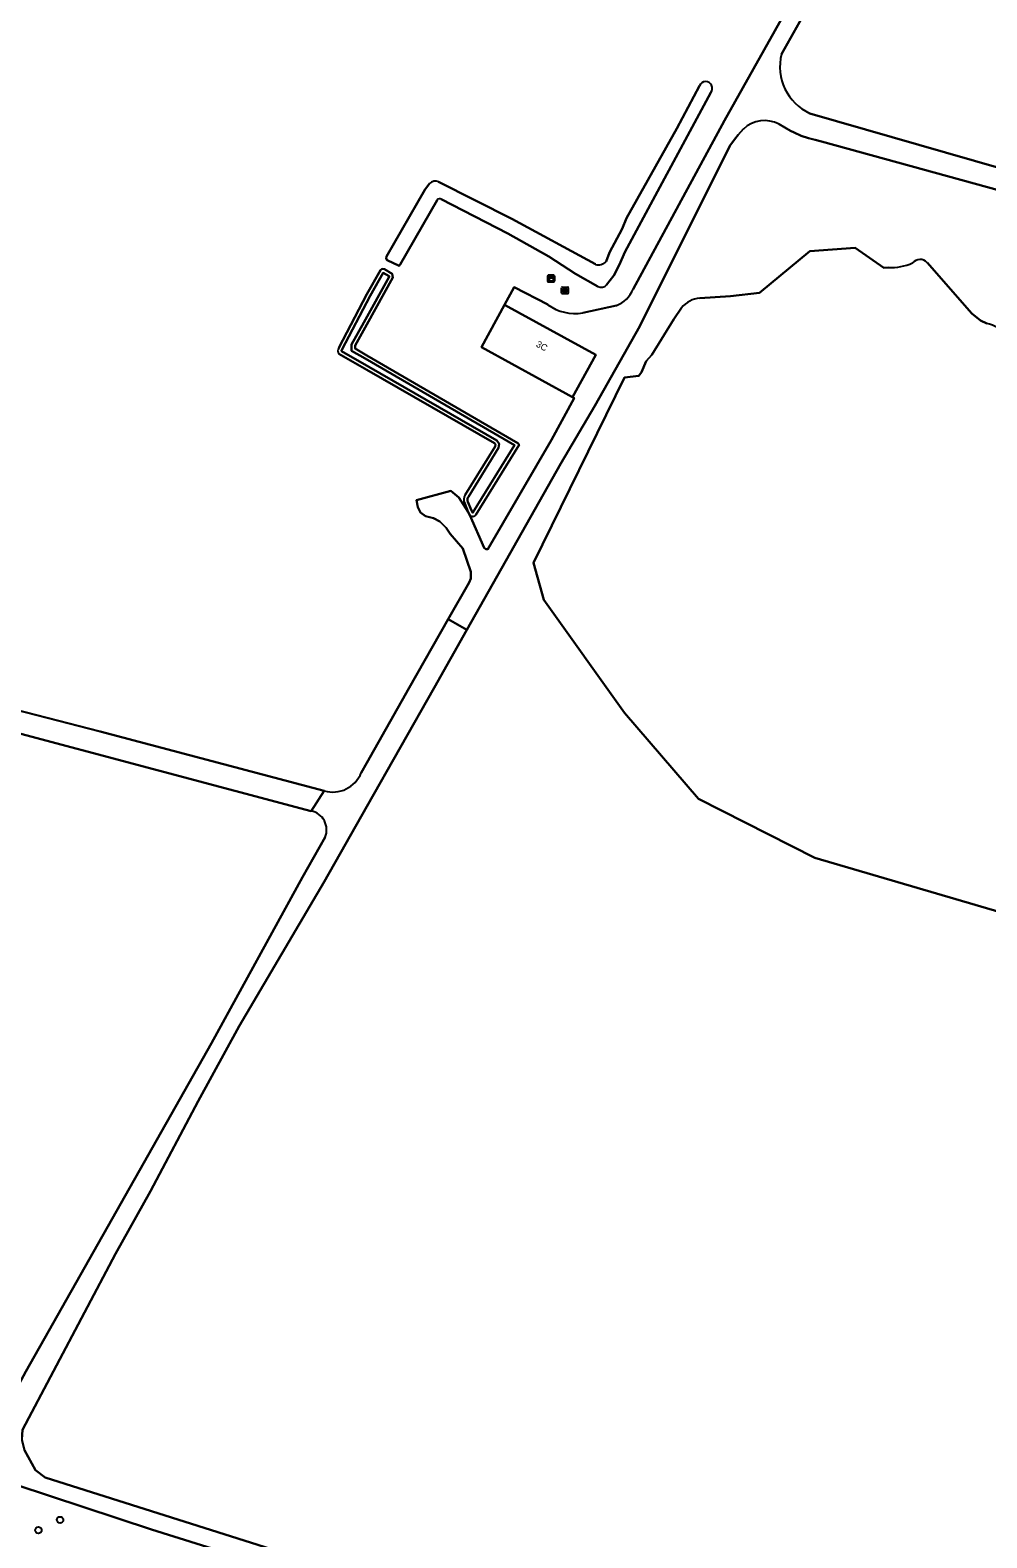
# Model space of a CAD drawing. Extents: x 156502 to 159075, y 384229 to 386100.
# Drawn here: x 157448.6 to 157594.6, y 384870.4 to 385100.3 of the extents above; entities that cross this region are included whole.
import ezdxf

# ---------------------------------------------------------------- set-up
doc = ezdxf.new("R2010")
doc.units = 0
for name, color, linetype in [('IMGEO_Boom', 7, 'Continuous'), ('IMGEO_Gemengd_bos', 7, 'Continuous'), ('IMGEO_Greppel_droge_sloot', 7, 'Continuous'), ('IMGEO_Kast', 7, 'Continuous'), ('IMGEO_Loofbos', 7, 'Continuous'), ('IMGEO_Meer_plas_ven_vijver', 7, 'Continuous'), ('IMGEO_Oever', 7, 'Continuous'), ('IMGEO_Pand', 7, 'Continuous'), ('IMGEO_Pand_nummerreeks', 7, 'Continuous'), ('IMGEO_Rijbaan_lokaal_gesloten', 7, 'Continuous'), ('IMGEO_Rijbaan_lokaal_onverhard', 7, 'Continuous'), ('IMGEO_Rioolput', 7, 'Continuous'), ('IMGEO_Voetpad_onverhard', 7, 'Continuous')]:
    doc.layers.add(name, color=color, linetype=linetype)

msp = doc.modelspace()

# ---------------------------------------------------------------- linework, layer by layer
at = {"layer": 'IMGEO_Boom'}
for centre in [(157453.19, 384873.13), (157449.89, 384871.57)]:
    msp.add_circle(centre, 0.489, dxfattribs=at)
at = {"layer": 'IMGEO_Gemengd_bos'}
for points in [[(157619.03, 385198.31), (157603.77, 385169.97), (157595.58, 385155.12), (157590.55, 385145.45), (157589.49, 385143.45), (157567.34, 385103.96), (157563.24, 385096.66)], [(157554.56, 385086.54), (157565.02, 385105.23), (157569.42, 385113.09), (157500, 385132.38), (157470.27, 385140.64), (157454.36, 385144.87), (157448.51, 385145.98)], [(157536.51, 385065.03), (157537.01, 385066.38), (157538.91, 385069.99), (157539.6, 385071.63), (157547.26, 385085.3), (157550.73, 385091.84)], [(157552.46, 385090.81), (157539.32, 385066.46), (157538.54, 385064.55), (157537.65, 385062.89), (157536.56, 385061.49)], [(157540.59, 385060.8), (157554.56, 385086.54)], [(157567.57, 385087.61), (157596.76, 385079.21), (157621.45, 385071.9), (157659.74, 385061.09), (157700.37, 385049.93), (157754.96, 385035.18)], [(157557.42, 385085.24), (157556.63, 385084.36), (157556.08, 385083.63), (157555.36, 385082.68), (157541.62, 385055.15), (157534.74, 385043), (157529.56, 385034.25), (157515.26, 385008.86), (157510.25, 385000), (157500, 384981.92), (157493.48, 384970.42), (157480.53, 384948.41), (157474.26, 384937.01), (157466.98, 384923.25), (157461.66, 384913.7), (157447.44, 384886.89), (157447.37, 384885.41), (157447.76, 384883.78), (157449.47, 384880.72), (157450.91, 384879.62), (157588.71, 384836)], [(157761.76, 385030.22), (157747.64, 385033.88), (157701.75, 385046.75), (157698.89, 385047.59), (157679.73, 385052.63), (157623.49, 385068.42), (157569.36, 385083.33), (157568.38, 385083.57), (157567.38, 385083.83), (157566.24, 385084.2), (157565.17, 385084.7), (157564.62, 385084.98), (157563.75, 385085.49), (157562.86, 385085.96)], [(157510.71, 385074.39), (157505.07, 385064.55), (157504.9, 385064.37), (157503.11, 385065.26), (157502.95, 385065.5), (157503.01, 385065.78), (157508.81, 385075.97), (157509.56, 385076.91)], [(157510.93, 385077.18), (157522.12, 385071.55), (157534.85, 385064.6)], [(157535.23, 385061.24), (157531.83, 385063.14), (157527.77, 385065.77), (157521.5, 385069.31), (157511.34, 385074.52)], [(157550.8, 385059.42), (157555.48, 385059.74), (157559.89, 385060.27), (157567.56, 385066.62), (157574.5, 385067.13), (157578.83, 385064.05), (157579.55, 385064.1)], [(157495.71, 385051.85), (157500, 385060.07), (157502.06, 385063.71), (157502.33, 385063.89), (157502.66, 385063.85), (157503.86, 385063.13), (157503.97, 385062.59), (157500, 385055.45), (157498.21, 385052.24), (157498.21, 385051.74), (157500, 385050.7), (157523.04, 385037.34), (157523.2, 385037.07), (157516.63, 385026.42)], [(157585.44, 385064.86), (157592.25, 385057.12), (157593.58, 385056.04), (157594.56, 385055.57)], [(157515.72, 385026.34), (157517.86, 385021.39), (157518.12, 385021.15), (157518.42, 385021.19), (157528.15, 385037.83), (157531.62, 385044.19), (157531.37, 385044.36), (157517.47, 385051.98), (157521.01, 385058.43), (157522.48, 385061.11), (157527.58, 385058.45)], [(157604.79, 384970.83), (157604.56, 384970.51), (157602.5, 384964.09), (157568.33, 384974.11), (157550.6, 384983.1), (157539.29, 384996.21), (157526.96, 385013.43), (157525.42, 385019.08), (157539.29, 385047.34), (157541.49, 385047.59), (157541.86, 385048.15), (157542.61, 385049.83), (157543.45, 385050.79), (157546.8, 385056.26), (157547.98, 385057.95)], [(157532.92, 385057.18), (157538.06, 385058.32)], [(157515.01, 385029.45), (157519.56, 385036.83), (157519.6, 385037.11), (157519.44, 385037.35), (157500, 385048.52), (157495.74, 385050.96)], [(157499.14, 384987.07), (157500, 384988.58), (157506.45, 385000), (157512.38, 385010.47), (157515.58, 385016.07), (157515.85, 385016.71), (157515.85, 385017.73), (157514.62, 385021.26), (157512.72, 385023.49), (157512.1, 385024.43), (157511.14, 385025.37), (157510.15, 385025.89), (157508.93, 385026.22), (157508.18, 385026.78), (157507.79, 385027.58), (157507.58, 385028.62), (157512.78, 385030.05), (157514.01, 385029.03), (157515.45, 385026.82), (157514.91, 385028.14)], [(157433.42, 385000), (157459.32, 384993.37), (157493.49, 384984.32)]]:
    msp.add_lwpolyline(points, dxfattribs=at)
for centre, radius, start, end in [((157570.83, 385094.73), 7.83, 165.6966, 245.3534), ((157551.67, 385091.45), 1.02, 320.75, 157.7513), ((157560.63, 385081.87), 4.65, 61.3849, 133.6498), ((157510.43, 385076.1), 1.19, 64.7657, 137.0208), ((157511.09, 385074.15), 0.449, 55.8892, 148.6329), ((157535.32, 385066.21), 1.68, 253.8994, 315.2296), ((157579.8, 385072.58), 8.49, 268.2806, 293.8488), ((157584.35, 385063.89), 1.45, 41.8437, 140.3958), ((157535.75, 385062.14), 1.04, 239.4436, 321.2719), ((157536.29, 385062.65), 4.69, 292.2098, 336.6936), ((157551, 385055.59), 3.84, 92.8928, 141.9271), ((157531.79, 385064.29), 7.2, 234.2693, 279.0667), ((157592.67, 385048.11), 7.7, 49.5127, 75.8056), ((157496.32, 385051.43), 0.741, 145.3523, 218.5394), ((157516.02, 385028.72), 1.25, 144.2193, 207.5408), ((157516.14, 385026.77), 0.602, 225.6527, 325.0861), ((157494.79, 384988.82), 4.69, 253.7973, 338.0784)]:
    msp.add_arc(centre, radius, start, end, dxfattribs=at)
at = {"layer": 'IMGEO_Greppel_droge_sloot'}
for points in [[(157550.73, 385091.84), (157547.26, 385085.3), (157539.6, 385071.63), (157538.91, 385069.99), (157537.01, 385066.38), (157536.51, 385065.03)], [(157536.56, 385061.49), (157537.65, 385062.89), (157538.54, 385064.55), (157539.32, 385066.46), (157552.46, 385090.81)], [(157509.56, 385076.91), (157508.81, 385075.97), (157503.01, 385065.78), (157502.95, 385065.5), (157503.11, 385065.26), (157504.9, 385064.37), (157505.07, 385064.55), (157510.71, 385074.39)], [(157534.85, 385064.6), (157522.12, 385071.55), (157510.93, 385077.18)], [(157511.34, 385074.52), (157521.5, 385069.31), (157527.77, 385065.77), (157531.83, 385063.14), (157535.23, 385061.24)]]:
    msp.add_lwpolyline(points, dxfattribs=at)
msp.add_lwpolyline([(157496.14, 385051.37), (157500.28, 385048.99), (157519.83, 385037.76), (157520.18, 385037.24), (157520.09, 385036.64), (157515.47, 385029.14), (157515.43, 385029.08), (157515.4, 385029.03), (157515.37, 385028.97), (157515.35, 385028.91), (157515.34, 385028.85), (157515.33, 385028.79), (157515.33, 385028.73), (157515.33, 385028.67), (157515.33, 385028.61), (157515.35, 385028.55), (157515.36, 385028.49), (157515.39, 385028.43), (157515.41, 385028.38), (157515.95, 385027.06), (157516.14, 385026.72), (157516.14, 385026.72), (157516.15, 385026.72), (157516.15, 385026.72), (157516.15, 385026.72), (157516.16, 385026.73), (157516.16, 385026.73), (157516.17, 385026.73), (157516.17, 385026.73), (157516.17, 385026.73), (157516.18, 385026.74), (157522.51, 385037.01), (157499.72, 385050.22), (157497.66, 385051.42), (157497.66, 385052.38), (157499.52, 385055.72), (157503.39, 385062.68), (157503.37, 385062.78), (157502.47, 385063.31), (157500.49, 385059.8), (157496.18, 385051.55), (157496.17, 385051.54), (157496.16, 385051.53), (157496.15, 385051.51), (157496.14, 385051.5), (157496.14, 385051.48), (157496.13, 385051.47), (157496.13, 385051.45), (157496.13, 385051.43), (157496.13, 385051.42), (157496.13, 385051.4), (157496.13, 385051.39)], close=True, dxfattribs=at)
for centre, radius, start, end in [((157551.67, 385091.45), 1.02, 320.75, 157.7513), ((157510.43, 385076.1), 1.19, 64.7657, 137.0208), ((157511.09, 385074.15), 0.449, 55.8892, 148.6329), ((157535.32, 385066.21), 1.68, 253.8994, 315.2296), ((157535.75, 385062.14), 1.04, 239.4436, 321.2719)]:
    msp.add_arc(centre, radius, start, end, dxfattribs=at)
at = {"layer": 'IMGEO_Kast'}
for p, q in [((157527.59, 385062), (157527.59, 385062.84)), ((157527.59, 385062.84), (157527.59, 385062)), ((157527.67, 385062.93), (157528.51, 385062.93)), ((157528.51, 385062.93), (157527.67, 385062.93)), ((157528.52, 385061.93), (157527.68, 385061.93)), ((157527.68, 385061.93), (157528.52, 385061.93)), ((157528.59, 385062.85), (157528.59, 385062.01)), ((157528.59, 385062.01), (157528.59, 385062.85))]:
    msp.add_line(p, q, dxfattribs=at)
for points in [[(157527.79, 385062.72), (157528.39, 385062.72), (157528.39, 385062.63), (157527.79, 385062.63), (157527.79, 385062.72)], [(157527.79, 385062.54), (157528.39, 385062.54), (157528.39, 385062.05), (157527.79, 385062.05), (157527.79, 385062.54)]]:
    msp.add_lwpolyline(points, dxfattribs=at)
msp.add_circle((157527.87, 385062.39), 0.0377, dxfattribs=at)
for centre, start, end in [((157527.67, 385062.85), 92.4484, 184.2845), ((157527.67, 385062.85), 92.4484, 184.2845), ((157527.67, 385062), 182.4484, 274.2845), ((157527.67, 385062), 182.4484, 274.2845), ((157528.51, 385062.85), 2.4484, 94.2845), ((157528.51, 385062.85), 2.4484, 94.2845), ((157528.51, 385062), 272.4484, 4.2845), ((157528.51, 385062), 272.4484, 4.2845)]:
    msp.add_arc(centre, 0.0779, start, end, dxfattribs=at)
at = {"layer": 'IMGEO_Loofbos'}
for points in [[(157491.51, 384981.23), (157420.82, 385000), (157402.98, 385004.83), (157378.76, 385010.68), (157366.24, 385014.04), (157353.42, 385017.05), (157331.74, 385022.85), (157308.57, 385028.04), (157267.28, 385036.51), (157263.05, 385038.24), (157261.91, 385039.31), (157260.91, 385040.83), (157260.53, 385041.15), (157260.11, 385041.15), (157259.87, 385040.93), (157259.81, 385040.65), (157258.77, 385026.18), (157257.73, 385007.37), (157257.48, 385000)], [(157490.19, 384971.17), (157493.64, 384977.25)], [(157442.88, 384886.43), (157447.96, 384895.79), (157476.29, 384945.81), (157490.19, 384971.17)], [(157982.38, 384710.15), (157890.46, 384738.65), (157832.02, 384757.28), (157744.01, 384785.34), (157707.84, 384796.24), (157675.78, 384806.29), (157630.86, 384820.37), (157467.13, 384871.68), (157446.5, 384878.49)]]:
    msp.add_lwpolyline(points, dxfattribs=at)
msp.add_arc((157490.94, 384978.37), 2.92, 337.538, 78.7624, dxfattribs=at)
at = {"layer": 'IMGEO_Meer_plas_ven_vijver'}
for points in [[(157579.55, 385064.1), (157578.83, 385064.05), (157574.5, 385067.13), (157567.56, 385066.62), (157559.89, 385060.27), (157555.48, 385059.74), (157550.8, 385059.42)], [(157594.56, 385055.57), (157593.58, 385056.04), (157592.25, 385057.12), (157585.44, 385064.86)], [(157547.98, 385057.95), (157546.8, 385056.26), (157543.45, 385050.79), (157542.61, 385049.83), (157541.86, 385048.15), (157541.49, 385047.59), (157539.29, 385047.34), (157525.42, 385019.08), (157526.96, 385013.43), (157539.29, 384996.21), (157550.6, 384983.1), (157568.33, 384974.11), (157602.5, 384964.09), (157604.56, 384970.51), (157604.79, 384970.83)]]:
    msp.add_lwpolyline(points, dxfattribs=at)
for centre, radius, start, end in [((157579.8, 385072.58), 8.49, 268.2806, 293.8488), ((157584.35, 385063.89), 1.45, 41.8437, 140.3958), ((157551, 385055.59), 3.84, 92.8928, 141.9271), ((157592.67, 385048.11), 7.7, 49.5127, 75.8056)]:
    msp.add_arc(centre, radius, start, end, dxfattribs=at)
at = {"layer": 'IMGEO_Oever'}
for points in [[(157500, 385050.7), (157498.21, 385051.74), (157498.21, 385052.24), (157500, 385055.45), (157503.97, 385062.59), (157503.86, 385063.13), (157502.66, 385063.85), (157502.33, 385063.89), (157502.06, 385063.71), (157500, 385060.07), (157495.71, 385051.85)], [(157495.74, 385050.96), (157500, 385048.52), (157519.44, 385037.35), (157519.6, 385037.11), (157519.56, 385036.83), (157515.01, 385029.45)], [(157516.63, 385026.42), (157523.2, 385037.07), (157523.04, 385037.34), (157500, 385050.7)], [(157514.91, 385028.14), (157515.45, 385026.82), (157515.72, 385026.34)]]:
    msp.add_lwpolyline(points, dxfattribs=at)
msp.add_lwpolyline([(157496.14, 385051.37), (157496.13, 385051.39), (157496.13, 385051.4), (157496.13, 385051.42), (157496.13, 385051.43), (157496.13, 385051.45), (157496.13, 385051.47), (157496.14, 385051.48), (157496.14, 385051.5), (157496.15, 385051.51), (157496.16, 385051.53), (157496.17, 385051.54), (157496.18, 385051.55), (157500.49, 385059.8), (157502.47, 385063.31), (157503.37, 385062.78), (157503.39, 385062.68), (157499.52, 385055.72), (157497.66, 385052.38), (157497.66, 385051.42), (157499.72, 385050.22), (157522.51, 385037.01), (157516.18, 385026.74), (157516.17, 385026.73), (157516.17, 385026.73), (157516.17, 385026.73), (157516.16, 385026.73), (157516.16, 385026.73), (157516.15, 385026.72), (157516.15, 385026.72), (157516.15, 385026.72), (157516.14, 385026.72), (157516.14, 385026.72), (157515.95, 385027.06), (157515.41, 385028.38), (157515.39, 385028.43), (157515.36, 385028.49), (157515.35, 385028.55), (157515.33, 385028.61), (157515.33, 385028.67), (157515.33, 385028.73), (157515.33, 385028.79), (157515.34, 385028.85), (157515.35, 385028.91), (157515.37, 385028.97), (157515.4, 385029.03), (157515.43, 385029.08), (157515.47, 385029.14), (157520.09, 385036.64), (157520.18, 385037.24), (157519.83, 385037.76), (157500.28, 385048.99)], close=True, dxfattribs=at)
for centre, radius, start, end in [((157496.32, 385051.43), 0.741, 145.3523, 218.5394), ((157516.02, 385028.72), 1.25, 144.2193, 207.5408), ((157516.14, 385026.77), 0.602, 225.6527, 325.0861)]:
    msp.add_arc(centre, radius, start, end, dxfattribs=at)
at = {"layer": 'IMGEO_Pand'}
msp.add_lwpolyline([(157531.37, 385044.36), (157534.91, 385050.81), (157521.01, 385058.43), (157517.47, 385051.98)], close=True, dxfattribs=at)
at = {"layer": 'IMGEO_Rijbaan_lokaal_gesloten'}
for points in [[(157563.24, 385096.66), (157567.34, 385103.96), (157565.02, 385105.23), (157554.56, 385086.54), (157540.59, 385060.8)], [(157621.45, 385071.9), (157596.76, 385079.21), (157567.57, 385087.61)], [(157527.58, 385058.45), (157522.48, 385061.11), (157521.01, 385058.43), (157534.91, 385050.81), (157531.37, 385044.36), (157531.62, 385044.19), (157528.15, 385037.83), (157518.42, 385021.19), (157518.12, 385021.15), (157517.86, 385021.39), (157515.72, 385026.34), (157515.45, 385026.82), (157514.01, 385029.03), (157512.78, 385030.05), (157507.58, 385028.62), (157507.79, 385027.58), (157508.18, 385026.78), (157508.93, 385026.22), (157510.15, 385025.89), (157511.14, 385025.37), (157512.1, 385024.43), (157512.72, 385023.49), (157514.62, 385021.26), (157515.85, 385017.73), (157515.85, 385016.71), (157515.58, 385016.07), (157512.38, 385010.47), (157515.26, 385008.86), (157529.56, 385034.25), (157534.74, 385043), (157541.62, 385055.15), (157555.36, 385082.68), (157556.08, 385083.63), (157556.63, 385084.36), (157557.42, 385085.24)], [(157562.86, 385085.96), (157563.75, 385085.49), (157564.62, 385084.98), (157565.17, 385084.7), (157566.24, 385084.2), (157567.38, 385083.83), (157568.38, 385083.57), (157569.36, 385083.33), (157623.49, 385068.42), (157679.73, 385052.63), (157698.89, 385047.59), (157701.75, 385046.75), (157747.64, 385033.88), (157761.76, 385030.22)], [(157538.06, 385058.32), (157532.92, 385057.18)]]:
    msp.add_lwpolyline(points, dxfattribs=at)
for centre, radius, start, end in [((157570.83, 385094.73), 7.83, 165.6966, 245.3534), ((157560.63, 385081.87), 4.65, 61.3849, 133.6498), ((157536.29, 385062.65), 4.69, 292.2098, 336.6936), ((157531.79, 385064.29), 7.2, 234.2693, 279.0667)]:
    msp.add_arc(centre, radius, start, end, dxfattribs=at)
at = {"layer": 'IMGEO_Rijbaan_lokaal_onverhard'}
msp.add_lwpolyline([(157420.82, 385000), (157491.51, 384981.23), (157493.49, 384984.32), (157459.32, 384993.37), (157433.42, 385000)], dxfattribs=at)
at = {"layer": 'IMGEO_Rioolput'}
for p, q in [((157529.7, 385060.19), (157529.7, 385061.04)), ((157529.77, 385061.11), (157530.63, 385061.11)), ((157530.63, 385060.11), (157529.77, 385060.11)), ((157529.96, 385060.61), (157529.96, 385060.62)), ((157530, 385060.66), (157530.4, 385060.66)), ((157530.4, 385060.57), (157530, 385060.57)), ((157530.21, 385060.33), (157530.18, 385060.33)), ((157530.19, 385060.89), (157530.21, 385060.89)), ((157530.44, 385060.62), (157530.44, 385060.61)), ((157530.7, 385061.04), (157530.7, 385060.19))]:
    msp.add_line(p, q, dxfattribs=at)
for points in [[(157529.7, 385060.19), (157529.7, 385061.04)], [(157529.77, 385061.11), (157530.63, 385061.11)], [(157530.63, 385060.11), (157529.77, 385060.11)], [(157530.7, 385061.04), (157530.7, 385060.19)]]:
    msp.add_lwpolyline(points, dxfattribs=at)
for centre, radius, start, end in [((157529.78, 385061.04), 0.0765, 91.552, 178.448), ((157529.78, 385061.04), 0.0765, 91.552, 178.448), ((157529.78, 385060.19), 0.0765, 181.552, 268.448), ((157529.78, 385060.19), 0.0765, 181.552, 268.448), ((157530, 385060.62), 0.0403, 85.8775, 175.7526), ((157529.99, 385060.61), 0.0366, 178.938, 274.7102), ((157530.4, 385060.62), 0.0386, 1.7309, 96.639), ((157530.4, 385060.61), 0.043, 264.8664, 352.4533), ((157530.62, 385061.04), 0.0765, 1.552, 88.448), ((157530.62, 385061.04), 0.0765, 1.552, 88.448), ((157530.62, 385060.19), 0.0765, 271.552, 358.448), ((157530.62, 385060.19), 0.0765, 271.552, 358.448)]:
    msp.add_arc(centre, radius, start, end, dxfattribs=at)
for centre, major_axis, ratio, start_param, end_param in [((157530.19, 385060.61), (-0.387, 0.002), 0.722429, 4.712389, 7.853982), ((157530.21, 385060.61), (-0.39, 0.002), 0.717154, 1.570796, 4.712389)]:
    msp.add_ellipse(centre, major_axis=major_axis, ratio=ratio, start_param=start_param, end_param=end_param, dxfattribs=at)
at = {"layer": 'IMGEO_Voetpad_onverhard'}
for points in [[(157466.98, 384923.25), (157474.26, 384937.01), (157480.53, 384948.41), (157493.48, 384970.42), (157500, 384981.92), (157510.25, 385000), (157515.26, 385008.86), (157512.38, 385010.47), (157506.45, 385000), (157500, 384988.58), (157499.14, 384987.07)], [(157493.49, 384984.32), (157491.51, 384981.23)], [(157493.64, 384977.25), (157490.19, 384971.17), (157476.29, 384945.81), (157447.96, 384895.79), (157442.88, 384886.43)], [(157446.5, 384878.49), (157467.13, 384871.68), (157630.86, 384820.37), (157675.78, 384806.29), (157707.84, 384796.24), (157744.01, 384785.34), (157832.02, 384757.28), (157890.46, 384738.65), (157982.38, 384710.15), (157983.05, 384711.86), (157983.84, 384713.24), (157904.05, 384737.06), (157848.04, 384754.92), (157684.73, 384806.26), (157588.71, 384836), (157450.91, 384879.62), (157449.47, 384880.72), (157447.76, 384883.78), (157447.37, 384885.41), (157447.44, 384886.89), (157461.66, 384913.7), (157466.98, 384923.25)]]:
    msp.add_lwpolyline(points, dxfattribs=at)
for centre, radius, start, end in [((157494.79, 384988.82), 4.69, 253.7973, 338.0784), ((157490.94, 384978.37), 2.92, 337.538, 78.7624)]:
    msp.add_arc(centre, radius, start, end, dxfattribs=at)

# ---------------------------------------------------------------- texts
at = {"layer": 'IMGEO_Pand_nummerreeks'}
msp.add_text('3C', height=1, rotation=331.2546, dxfattribs=at).set_placement((157525.7, 385052.12))

doc.saveas('drawing.dxf')
